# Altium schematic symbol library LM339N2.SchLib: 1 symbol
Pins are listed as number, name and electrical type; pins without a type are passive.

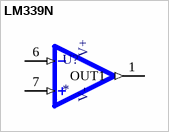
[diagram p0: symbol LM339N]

## LM339N
designator U?
Quad Voltage Comparators; MF: TAEJIN; MP: LM339N
footprint DIP764W47P254L1920H431Q14
pins: 1 OUT1 (out), 6 IN1- (in), 7 IN1+ (in)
